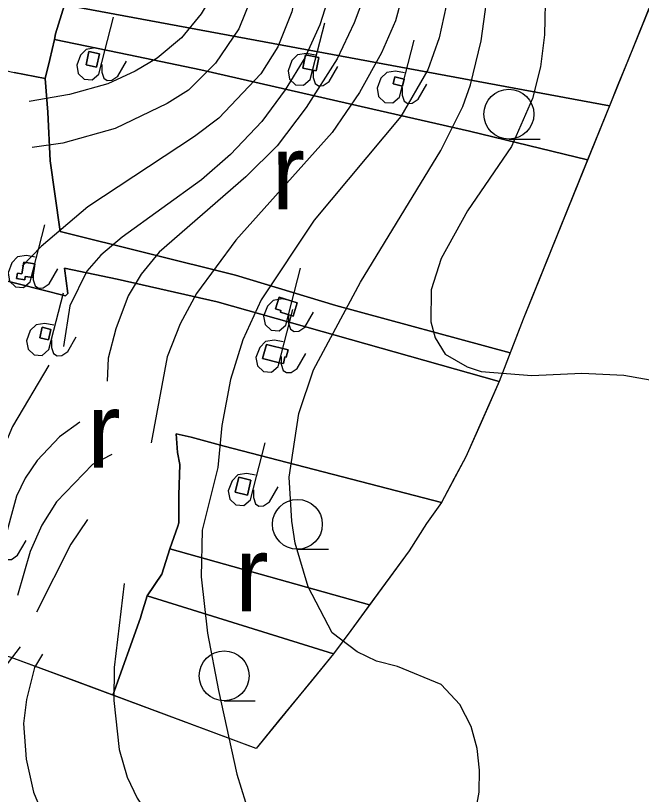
# Model space of a CAD drawing. Extents: x -1900516 to -575031, y -3809306 to -1157387.
# Drawn here: x -577722.1 to -577546.5, y -1161328.5 to -1161109.9 of the extents above; entities that cross this region are included whole.
import ezdxf

# ---------------------------------------------------------------- set-up
doc = ezdxf.new("R2010")
doc.units = 0
for name, color, linetype in [('01_OBVOD PÚ', 7, 'Continuous'), ('01_SPRÁV_HRANICE', 7, 'Continuous'), ('01_VRSTEVNICE', 7, 'Continuous'), ('02_KULTURY STAV', 7, 'Continuous')]:
    doc.layers.add(name, color=color, linetype=linetype)

msp = doc.modelspace()

# ---------------------------------------------------------------- linework, layer by layer
at = {"layer": '01_OBVOD PÚ'}
msp.add_lwpolyline([(-577536.34, -1161087.8), (-577579.71, -1161195.12), (-577586.41, -1161212.58), (-577595.83, -1161233.79), (-577602.65, -1161246.61), (-577606.83, -1161252.46), (-577611.73, -1161260.15), (-577628.1, -1161282.46), (-577632.96, -1161289.06), (-577654.64, -1161315.59), (-577704.91, -1161296.89), (-577723.33, -1161290.04), (-577738.87, -1161285.16), (-577741.11, -1161284.46), (-577791.55, -1161273.38), (-577796.53, -1161272.94), (-577801.98, -1161272.46), (-577805.05, -1161272.19), (-577811.48, -1161271.62), (-577812.83, -1161271.5), (-577826.04, -1161270.33), (-577828.91, -1161270.07), (-577971.47, -1161268.93)], dxfattribs=at)
at = {"layer": '01_SPRÁV_HRANICE'}
for p, q in [((-577543.3, -1161105.01), (-577550.03, -1161121.67)), ((-577550.03, -1161121.67), (-577553.12, -1161129.32)), ((-577553.12, -1161129.32), (-577555.51, -1161135.24)), ((-577555.51, -1161135.24), (-577561.64, -1161150.41)), ((-577561.64, -1161150.41), (-577564.41, -1161157.27)), ((-577564.41, -1161157.27), (-577567.29, -1161164.38)), ((-577567.29, -1161164.38), (-577577.02, -1161188.45)), ((-577577.02, -1161188.45), (-577579.71, -1161195.12)), ((-577579.71, -1161195.12), (-577583.34, -1161204.57)), ((-577583.34, -1161204.57), (-577586.41, -1161212.58)), ((-577586.41, -1161212.58), (-577589.36, -1161219.23)), ((-577589.36, -1161219.23), (-577592.28, -1161225.79)), ((-577592.28, -1161225.79), (-577595.83, -1161233.79)), ((-577595.83, -1161233.79), (-577599.06, -1161239.87)), ((-577599.06, -1161239.87), (-577602.65, -1161246.61)), ((-577602.65, -1161246.61), (-577606.83, -1161252.46)), ((-577606.83, -1161252.46), (-577611.73, -1161260.15)), ((-577611.73, -1161260.15), (-577617.06, -1161267.41)), ((-577617.06, -1161267.41), (-577622.08, -1161274.25)), ((-577622.08, -1161274.25), (-577628.1, -1161282.46)), ((-577628.1, -1161282.46), (-577632.96, -1161289.06)), ((-577704.77, -1161296.94), (-577723.33, -1161290.04)), ((-577632.96, -1161289.06), (-577639.04, -1161296.5)), ((-577654.64, -1161315.59), (-577704.77, -1161296.94)), ((-577639.04, -1161296.5), (-577648.32, -1161307.86)), ((-577648.32, -1161307.86), (-577654.64, -1161315.59))]:
    msp.add_line(p, q, dxfattribs=at)
at = {"layer": '01_VRSTEVNICE'}
for points in [[(-577637.23, -1160935.53), (-577659.75, -1160966.85), (-577666.46, -1160980.27), (-577669.53, -1160989.22), (-577671.11, -1160995.97), (-577671.21, -1161002.64), (-577667.58, -1161037.88), (-577663.1, -1161062.48), (-577661.98, -1161074.23), (-577662.26, -1161085.97), (-577664.5, -1161097.72), (-577666.22, -1161102.89), (-577670.09, -1161109.46), (-577675.55, -1161116.17), (-577682.4, -1161121.91), (-577688.55, -1161125.54), (-577696.24, -1161129.04), (-577707.01, -1161132.11), (-577718.33, -1161134.07)], [(-577623.95, -1160946.57), (-577633.6, -1160955.94), (-577645.2, -1160966.01), (-577653.45, -1160974.96), (-577657.51, -1160980.83), (-577659.89, -1160986.7), (-577661.28, -1160992.57), (-577662.54, -1161005.72), (-577658.91, -1161039.27), (-577652.75, -1161074.51), (-577652.61, -1161092.12), (-577653.73, -1161098), (-577656.13, -1161105.26), (-577659.47, -1161113.66), (-577666.04, -1161123.3), (-577673.59, -1161130.86), (-577679.6, -1161134.63), (-577694.14, -1161141.62), (-577708.82, -1161145.68), (-577717.49, -1161146.94)], [(-577606.75, -1160947.97), (-577616.4, -1160957.48), (-577633.18, -1160971.46), (-577641.99, -1160980.97), (-577647.58, -1160989.5), (-577649.82, -1160994.23), (-577650.52, -1160998.45), (-577651.08, -1161007.11), (-577650.38, -1161015.5), (-577643.39, -1161053.26), (-577641.57, -1161070.03), (-577641.85, -1161091.01), (-577642.83, -1161099.4), (-577644.62, -1161108.89), (-577648.56, -1161118.69), (-577653.31, -1161126.24), (-577665.06, -1161138.69), (-577671.91, -1161143.86), (-577701.83, -1161163.57), (-577714.97, -1161174.76), (-577720.29, -1161180.21)], [(-577585.78, -1160950.35), (-577591.93, -1160959.85), (-577600.6, -1160971.32), (-577611.93, -1160984.74), (-577618.64, -1160994.53), (-577623.11, -1161004.04), (-577625.22, -1161010.8), (-577625.77, -1161017.46), (-577625.07, -1161037.59), (-577621.3, -1161065.28), (-577620.88, -1161080.1), (-577622.69, -1161096.88), (-577624.27, -1161104.15), (-577627.17, -1161111.98), (-577631.92, -1161122.05), (-577640.59, -1161135.75), (-577648.7, -1161146.52), (-577657.51, -1161155.18), (-577681.84, -1161176.3), (-577686.87, -1161182.45), (-577690.51, -1161188.6), (-577694, -1161197.83), (-577696.1, -1161206.08), (-577696.38, -1161212.51)], [(-577576.83, -1160950.63), (-577583.82, -1160964.05), (-577591.37, -1160975.24), (-577599.29, -1160983.66), (-577607.59, -1160993.55), (-577613.05, -1161004.04), (-577615.12, -1161011.28), (-577616.12, -1161019.7), (-577614.86, -1161042.07), (-577610.53, -1161073.39), (-577610.25, -1161084.57), (-577611.37, -1161095.76), (-577615.56, -1161111.42), (-577619.48, -1161120.37), (-577625.63, -1161131.55), (-577633.32, -1161142.74), (-577660.31, -1161172.94), (-577671.35, -1161187.9), (-577675.96, -1161196.43), (-577679.6, -1161205.66), (-577684.08, -1161229.85)], [(-577598.36, -1160954.26), (-577621.71, -1160978.45), (-577628.43, -1160986.7), (-577633.6, -1160995.65), (-577635.78, -1161001.18), (-577636.68, -1161008.23), (-577636.68, -1161017.18), (-577632.2, -1161052.98), (-577630.24, -1161076.47), (-577630.52, -1161088.21), (-577631.78, -1161096.04), (-577634.02, -1161103.87), (-577636.73, -1161112.52), (-577641.01, -1161121.77), (-577646.46, -1161130.72), (-577653.03, -1161139.66), (-577661.84, -1161148.89), (-577669.95, -1161156.02), (-577692.18, -1161172.1), (-577698.2, -1161177.14), (-577702.11, -1161181.61), (-577706.86, -1161191.4), (-577708.67, -1161202.76)], [(-577593.19, -1161334.02), (-577592.07, -1161327.86), (-577591.93, -1161321.71), (-577592.63, -1161315.56), (-577594.31, -1161309.41), (-577597.53, -1161303.26), (-577602.7, -1161297.66), (-577615, -1161292.63), (-577620.88, -1161291.09), (-577626.33, -1161288.43), (-577633.32, -1161283.12), (-577640.03, -1161270.26), (-577643.67, -1161257.95), (-577644.65, -1161251.8), (-577645.34, -1161239.5), (-577642.69, -1161221.6), (-577638.49, -1161209.29), (-577625.35, -1161184.69), (-577602.84, -1161147.77), (-577596.69, -1161135.47), (-577594.45, -1161129.32), (-577591.51, -1161117.01), (-577589, -1161098.56)], [(-577573.48, -1161101.91), (-577573.76, -1161115.34), (-577574.87, -1161124.28), (-577577.11, -1161133.23), (-577582.98, -1161146.66), (-577595.29, -1161164.69), (-577602.7, -1161178.11), (-577605.49, -1161186.92), (-577605.64, -1161195.87), (-577604.38, -1161200.35), (-577601.58, -1161204.96), (-577595.43, -1161208.46), (-577591.51, -1161209.85), (-577577.25, -1161210.97), (-577563.27, -1161210.27), (-577551.52, -1161210.83), (-577541.46, -1161212.65)], [(-577601.3, -1161107.23), (-577603.26, -1161116.18), (-577606.47, -1161125.12), (-577614.02, -1161138.27), (-577638.35, -1161167.35), (-577653.17, -1161189.72), (-577658.35, -1161200.91), (-577661.84, -1161212.09), (-577664.22, -1161224.96), (-577665.34, -1161236.7), (-577669.81, -1161254.32), (-577670.09, -1161267.46), (-577668.28, -1161283.28), (-577665.2, -1161299.34), (-577660.03, -1161322.83), (-577656.39, -1161334.57)], [(-577712.74, -1161208.04), (-577722.94, -1161225.24), (-577726.16, -1161232.78), (-577728.82, -1161242.85), (-577731.05, -1161260.47), (-577730.77, -1161264.52), (-577732.59, -1161273.05), (-577735.39, -1161279.21), (-577736.51, -1161280.6), (-577740.42, -1161285.92), (-577745.59, -1161297.1), (-577753.43, -1161321.71), (-577754.96, -1161330.66), (-577755.66, -1161341.84), (-577753.84, -1161373.3)], [(-577704.07, -1161223.98), (-577709.8, -1161228.17), (-577716.09, -1161234.74), (-577719.45, -1161239.78), (-577721.83, -1161244.81), (-577725.6, -1161258.51), (-577726.58, -1161271.79)], [(-577695.12, -1161233.06), (-577700.57, -1161235.86), (-577710.64, -1161246.35), (-577714.7, -1161252.92), (-577718.05, -1161260.33), (-577721.55, -1161272.63)], [(-577701.97, -1161251.38), (-577706.59, -1161258.23), (-577716.23, -1161277.39)], [(-577691.62, -1161269.28), (-577694.42, -1161292.91), (-577694.56, -1161302.14), (-577693.02, -1161315.84), (-577690.79, -1161323.67), (-577687.99, -1161329.54), (-577673.73, -1161351.07), (-577669.54, -1161358.79), (-577665.9, -1161367.57), (-577662.4, -1161382.67), (-577661.7, -1161391.06), (-577661.98, -1161395.68)], [(-577720.85, -1161287.04), (-577726.3, -1161294.31), (-577730.49, -1161303.81), (-577733.57, -1161313.88), (-577734.69, -1161325.63), (-577733.57, -1161335.41), (-577730.49, -1161346.6), (-577727.42, -1161354.71), (-577719.87, -1161369.81), (-577715.25, -1161384.91)], [(-577714.56, -1161289.13), (-577716.79, -1161292.91), (-577719.03, -1161301.86), (-577719.87, -1161308.57), (-577719.17, -1161318.64), (-577717.07, -1161327.86), (-577714.14, -1161334.85), (-577710.78, -1161340.59), (-577703.37, -1161350.37), (-577695.26, -1161359.46), (-577689.95, -1161367.85), (-577686.03, -1161377.92), (-577684.35, -1161390.64)]]:
    msp.add_lwpolyline(points, dxfattribs=at)
at = {"layer": '02_KULTURY STAV'}
for points in [[(-577543.29, -1161105.01), (-577555.51, -1161135.24), (-577708.42, -1161106.88), (-577710.87, -1161115.01), (-577711.2, -1161116.67), (-577712.49, -1161122.26), (-577713.77, -1161127.61), (-577722.52, -1161125.9)], [(-577697.29, -1161119.49), (-577699.79, -1161119.01), (-577702.29, -1161119.41), (-577703.91, -1161121.02), (-577704.95, -1161123.85), (-577704.55, -1161126.19), (-577702.85, -1161127.8), (-577700.6, -1161127.96), (-577698.74, -1161126.35), (-577694.63, -1161110.38)], [(-577638.01, -1161121.02), (-577640.51, -1161120.54), (-577643.01, -1161120.94), (-577644.62, -1161122.55), (-577645.68, -1161125.38), (-577645.27, -1161127.72), (-577643.58, -1161129.33), (-577641.32, -1161129.49), (-577639.46, -1161127.88), (-577635.35, -1161111.91)], [(-577613, -1161125.97), (-577615.5, -1161125.49), (-577618, -1161125.89), (-577619.61, -1161127.5), (-577620.67, -1161130.33), (-577620.26, -1161132.67), (-577618.57, -1161134.28), (-577616.31, -1161134.44), (-577614.45, -1161132.83), (-577610.34, -1161116.86)], [(-577697.93, -1161123.61), (-577697.93, -1161125.78), (-577697.37, -1161127.48), (-577696.4, -1161128.12), (-577695.11, -1161128.04), (-577693.42, -1161126.91), (-577691, -1161122.72)], [(-577638.65, -1161125.14), (-577638.65, -1161127.31), (-577638.09, -1161129.01), (-577637.12, -1161129.65), (-577635.83, -1161129.57), (-577634.14, -1161128.44), (-577631.72, -1161124.25)], [(-577613.64, -1161130.09), (-577613.64, -1161132.26), (-577613.08, -1161133.96), (-577612.11, -1161134.6), (-577610.82, -1161134.52), (-577609.13, -1161133.39), (-577606.71, -1161129.2)], [(-577583.71, -1161144.6), (-577574.96, -1161144.6)], [(-577716.57, -1161177.75), (-577719.07, -1161177.27), (-577721.57, -1161177.67), (-577723.19, -1161179.28), (-577724.23, -1161182.11), (-577723.83, -1161184.45), (-577722.14, -1161186.06), (-577719.88, -1161186.22), (-577718.02, -1161184.61), (-577713.91, -1161168.64)], [(-577767.95, -1161173.46), (-577708.08, -1161188.54), (-577707.43, -1161187.95), (-577708.34, -1161180.79), (-577693.64, -1161183.9), (-577665.53, -1161190.23), (-577586.41, -1161212.58), (-577595.83, -1161233.79), (-577602.65, -1161246.61), (-577663.55, -1161230.73), (-577672.85, -1161228.24), (-577677.02, -1161227.29), (-577676.65, -1161232.58), (-577676.06, -1161235.9), (-577676.35, -1161244.49), (-577676.31, -1161252.31), (-577676.63, -1161253.22), (-577678.84, -1161259.53), (-577681.04, -1161266.65), (-577685.18, -1161272.8), (-577686.74, -1161277.9), (-577687.04, -1161278.96), (-577694.8, -1161300.65), (-577704.91, -1161296.89), (-577723.33, -1161290.04)], [(-577717.21, -1161181.87), (-577717.21, -1161184.04), (-577716.65, -1161185.74), (-577715.68, -1161186.38), (-577714.39, -1161186.3), (-577712.7, -1161185.17), (-577710.28, -1161180.98)], [(-577644.87, -1161189.93), (-577647.37, -1161189.45), (-577649.87, -1161189.85), (-577651.48, -1161191.46), (-577652.54, -1161194.29), (-577652.13, -1161196.63), (-577650.44, -1161198.24), (-577648.18, -1161198.4), (-577646.32, -1161196.79), (-577642.21, -1161180.82)], [(-577711.36, -1161196.8), (-577713.86, -1161196.32), (-577716.36, -1161196.72), (-577717.97, -1161198.33), (-577719.03, -1161201.16), (-577718.62, -1161203.5), (-577716.93, -1161205.11), (-577714.67, -1161205.27), (-577712.81, -1161203.66), (-577708.7, -1161187.69)], [(-577647, -1161201.5), (-577649.5, -1161201.02), (-577652, -1161201.42), (-577653.61, -1161203.03), (-577654.67, -1161205.86), (-577654.26, -1161208.2), (-577652.57, -1161209.81), (-577650.31, -1161209.97), (-577648.45, -1161208.36), (-577644.34, -1161192.39)], [(-577645.51, -1161194.05), (-577645.51, -1161196.22), (-577644.95, -1161197.92), (-577643.98, -1161198.56), (-577642.69, -1161198.48), (-577641, -1161197.35), (-577638.58, -1161193.16)], [(-577712, -1161200.92), (-577712, -1161203.09), (-577711.44, -1161204.79), (-577710.47, -1161205.43), (-577709.18, -1161205.35), (-577707.49, -1161204.22), (-577705.07, -1161200.03)], [(-577647.64, -1161205.62), (-577647.64, -1161207.79), (-577647.08, -1161209.49), (-577646.11, -1161210.13), (-577644.82, -1161210.05), (-577643.13, -1161208.92), (-577640.71, -1161204.73)], [(-577654.77, -1161238.92), (-577657.27, -1161238.44), (-577659.77, -1161238.84), (-577661.39, -1161240.45), (-577662.44, -1161243.28), (-577662.03, -1161245.62), (-577660.33, -1161247.23), (-577658.08, -1161247.39), (-577656.22, -1161245.78), (-577652.11, -1161229.81)], [(-577655.41, -1161243.04), (-577655.41, -1161245.21), (-577654.85, -1161246.91), (-577653.88, -1161247.55), (-577652.59, -1161247.47), (-577650.9, -1161246.34), (-577648.48, -1161242.15)], [(-577726.09, -1161258.09), (-577726.09, -1161260.26), (-577725.53, -1161261.96), (-577724.56, -1161262.6), (-577723.27, -1161262.52), (-577721.58, -1161261.39), (-577719.16, -1161257.2)], [(-577643.06, -1161259.69), (-577634.31, -1161259.69)], [(-577663.61, -1161302.2), (-577654.86, -1161302.2)]]:
    msp.add_lwpolyline(points, dxfattribs=at)
for points in [[(-577711.2, -1161116.67), (-577710.87, -1161115.01), (-577708.42, -1161106.88), (-577555.51, -1161135.24), (-577561.64, -1161150.41), (-577594.79, -1161142.35), (-577621.85, -1161136.15), (-577670.12, -1161125.19), (-577690.38, -1161120.89)], [(-577713.77, -1161127.61), (-577712.49, -1161122.26), (-577711.2, -1161116.67), (-577690.38, -1161120.89), (-577670.12, -1161125.19), (-577621.85, -1161136.15), (-577594.79, -1161142.35), (-577561.64, -1161150.41), (-577579.71, -1161195.12), (-577583.34, -1161204.57), (-577632.25, -1161191.32), (-577660.4, -1161182.78), (-577709.62, -1161170.52), (-577711.08, -1161159.96), (-577712.44, -1161150.65), (-577713.08, -1161137.03)], [(-577713.77, -1161127.61), (-577712.49, -1161122.26), (-577711.2, -1161116.67), (-577690.38, -1161120.89), (-577670.12, -1161125.19), (-577621.85, -1161136.15), (-577594.79, -1161142.35), (-577561.64, -1161150.41), (-577579.71, -1161195.12), (-577583.34, -1161204.57), (-577632.25, -1161191.32), (-577660.4, -1161182.78), (-577709.62, -1161170.52), (-577711.08, -1161159.96), (-577712.44, -1161150.65), (-577713.08, -1161137.03)], [(-577713.77, -1161127.61), (-577712.49, -1161122.26), (-577711.2, -1161116.67), (-577690.38, -1161120.89), (-577670.12, -1161125.19), (-577621.85, -1161136.15), (-577594.79, -1161142.35), (-577561.64, -1161150.41), (-577579.71, -1161195.12), (-577583.34, -1161204.57), (-577632.25, -1161191.32), (-577660.4, -1161182.78), (-577709.62, -1161170.52), (-577711.08, -1161159.96), (-577712.44, -1161150.65), (-577713.08, -1161137.03)], [(-577713.77, -1161127.61), (-577712.49, -1161122.26), (-577711.2, -1161116.67), (-577690.38, -1161120.89), (-577670.12, -1161125.19), (-577621.85, -1161136.15), (-577594.79, -1161142.35), (-577561.64, -1161150.41), (-577579.71, -1161195.12), (-577583.34, -1161204.57), (-577632.25, -1161191.32), (-577660.4, -1161182.78), (-577709.62, -1161170.52), (-577711.08, -1161159.96), (-577712.44, -1161150.65), (-577713.08, -1161137.03)], [(-577768.87, -1161173.2), (-577766.09, -1161166.12), (-577758.39, -1161149.65), (-577753.54, -1161139.79), (-577747.42, -1161120.21), (-577722.52, -1161125.9), (-577713.77, -1161127.61), (-577713.08, -1161137.03), (-577712.44, -1161150.65), (-577711.08, -1161159.96), (-577709.62, -1161170.52), (-577660.4, -1161182.78), (-577632.25, -1161191.32), (-577583.34, -1161204.57), (-577586.41, -1161212.58), (-577665.53, -1161190.23), (-577693.64, -1161183.9), (-577708.34, -1161180.79), (-577707.43, -1161187.95), (-577708.08, -1161188.54), (-577767.95, -1161173.46)], [(-577702.34, -1161123.71), (-577699.42, -1161124.37), (-577698.6, -1161120.66), (-577701.52, -1161120)], [(-577702.34, -1161123.71), (-577699.42, -1161124.37), (-577698.6, -1161120.66), (-577701.52, -1161120)], [(-577702.34, -1161123.71), (-577699.42, -1161124.37), (-577698.6, -1161120.66), (-577701.52, -1161120)], [(-577702.34, -1161123.71), (-577701.52, -1161120), (-577698.6, -1161120.66), (-577699.42, -1161124.37)], [(-577702.34, -1161123.71), (-577699.42, -1161124.37), (-577698.6, -1161120.66), (-577701.52, -1161120)], [(-577641.49, -1161124.64), (-577637.77, -1161125.41), (-577637.07, -1161121.67), (-577640.79, -1161120.9)], [(-577641.49, -1161124.64), (-577640.79, -1161120.9), (-577637.07, -1161121.67), (-577637.77, -1161125.41)], [(-577616.19, -1161129.11), (-577613.56, -1161129.73), (-577613.1, -1161127.77), (-577615.73, -1161127.15)], [(-577616.19, -1161129.11), (-577615.73, -1161127.15), (-577613.1, -1161127.77), (-577613.56, -1161129.73)], [(-577721.83, -1161183.71), (-577719.52, -1161184.07), (-577719.38, -1161183.15), (-577717.31, -1161183.47), (-577716.71, -1161179.62), (-577719.8, -1161179.14), (-577720.31, -1161182.39), (-577721.59, -1161182.19)], [(-577721.83, -1161183.71), (-577721.59, -1161182.19), (-577720.31, -1161182.39), (-577719.8, -1161179.14), (-577716.71, -1161179.62), (-577717.31, -1161183.47), (-577719.38, -1161183.15), (-577719.52, -1161184.07)], [(-577649.17, -1161192.21), (-577647.69, -1161192.67), (-577647.83, -1161193.12), (-577644.27, -1161194.23), (-577643.08, -1161190.49), (-577646.66, -1161189.37), (-577648.14, -1161188.91)], [(-577649.17, -1161192.21), (-577648.14, -1161188.91), (-577646.66, -1161189.37), (-577643.08, -1161190.49), (-577644.27, -1161194.23), (-577647.83, -1161193.12), (-577647.69, -1161192.67)], [(-577715.35, -1161200.31), (-577712.9, -1161200.9), (-577712.2, -1161197.98), (-577714.65, -1161197.39)], [(-577715.35, -1161200.31), (-577714.65, -1161197.39), (-577712.2, -1161197.98), (-577712.9, -1161200.9)], [(-577652.82, -1161206.11), (-577648.07, -1161207.33), (-577646.94, -1161207.6), (-577646.54, -1161205.71), (-577646.2, -1161205.77), (-577645.63, -1161203.76), (-577651.7, -1161202.21)], [(-577652.82, -1161206.11), (-577651.7, -1161202.21), (-577645.63, -1161203.76), (-577646.2, -1161205.77), (-577646.54, -1161205.71), (-577646.94, -1161207.6), (-577648.07, -1161207.33)], [(-577678.84, -1161259.53), (-577676.63, -1161253.22), (-577676.31, -1161252.31), (-577676.35, -1161244.49), (-577676.06, -1161235.9), (-577676.65, -1161232.58), (-577677.02, -1161227.29), (-577672.85, -1161228.24), (-577663.55, -1161230.73), (-577602.65, -1161246.61), (-577606.83, -1161252.46), (-577611.73, -1161260.15), (-577622.83, -1161275.28)], [(-577660.47, -1161243.66), (-577657.05, -1161244.47), (-577656.08, -1161240.3), (-577659.5, -1161239.49)], [(-577660.47, -1161243.66), (-577659.5, -1161239.49), (-577656.08, -1161240.3), (-577657.05, -1161244.47)], [(-577685.18, -1161272.8), (-577681.04, -1161266.65), (-577678.84, -1161259.53), (-577622.83, -1161275.28), (-577628.1, -1161282.46), (-577632.96, -1161289.06)], [(-577685.18, -1161272.8), (-577681.04, -1161266.65), (-577678.84, -1161259.53), (-577622.83, -1161275.28), (-577628.1, -1161282.46), (-577632.96, -1161289.06)], [(-577694.8, -1161300.65), (-577687.04, -1161278.96), (-577686.74, -1161277.9), (-577685.18, -1161272.8), (-577632.96, -1161289.06), (-577654.64, -1161315.59)]]:
    msp.add_lwpolyline(points, close=True, dxfattribs=at)
for centre in [(-577583.71, -1161137.6), (-577643.06, -1161252.69), (-577663.61, -1161295.2)]:
    msp.add_circle(centre, 7, dxfattribs=at)

# ---------------------------------------------------------------- texts
for p in [(-577650.3, -1161164.27), (-577650.3, -1161164.27), (-577702.02, -1161236.76), (-577660.5, -1161277.07), (-577660.5, -1161277.07)]:
    msp.add_text('r', height=21, dxfattribs=at).set_placement(p)

doc.saveas('drawing.dxf')
